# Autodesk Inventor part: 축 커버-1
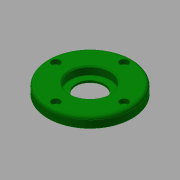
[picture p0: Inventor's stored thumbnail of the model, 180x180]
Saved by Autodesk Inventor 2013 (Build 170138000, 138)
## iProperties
Created: 2015-10
Part Number: 축 커버-1
Document SubType Name: Modeling
Designer: mdu
Density: 7.86 g/cm^3
Material: 강철, 연강
Mass: 322.464 g
Surface Area: 133.703 cm^2
Volume: 41.026 cm^3
Author: mdu
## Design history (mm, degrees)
sketch "스케치1"
  geometry: C1 r 40 at (0, 0) reference; C2 r 26 at (0, 0) reference; 1 further point
  node "참조1"
  node "참조2"
extrude "돌출1" new body sketch "스케치1" distance "d0" = 10; taper "d1" = 0 deg
extrude "돌출2" join sketch "스케치1" distance "d2" = 3; taper "d3" = 0 deg
hole "구멍1" diameter "d6" = 27; stored, may be unused: countersink angle "d10" = 90 deg, drill point angle "d12" = 118 deg; dims "d4" = 10, "d5" = 10, "d7" = 6, "d8" = 38, "d9" = 8, "d11" = 8
sketch "스케치2"
  geometry: C1 r 20 at (0, 0); 1 further point
  constraints: 1 centre point, 1 coincident
  dimensions: "d13" = 40 diameter of C1
extrude "돌출3" cut sketch "스케치2" distance "d14" = 3; taper "d15" = 0 deg
sketch "스케치3"
  geometry: C1 r 1.621 at (0, 32.5) reference; 1 further point
hole "구멍2" sketch "스케치3" at (0, 32.5) diameter "d16" = 4.5; stored, may be unused: countersink angle "d20" = 90 deg, drill point angle "d22" = 118 deg; dims "d17" = 6, "d18" = 8, "d19" = 4.4, "d21" = 8
fillet "모깎기1" dims "d26" = 3, "d27" = 0.3
chamfer "모따기1" distance "d28" = 1; stored, may be unused: second distance "d29" = 2, angle "d30" = 45 deg
node "솔리드1"
pattern_circular "원형 패턴1" dims angle "d24" = 360 deg
node "참조3"
